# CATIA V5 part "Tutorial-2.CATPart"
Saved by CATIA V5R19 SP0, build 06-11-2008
Part number: c11tut2
Bounding box of the stored display mesh (mm): x -175 to 0, y -36.667 to 105, z 0 to 36.632
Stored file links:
  D:\Shriniwas\v5_r19\Part files\c11\c11tut2.CATPart
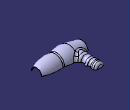
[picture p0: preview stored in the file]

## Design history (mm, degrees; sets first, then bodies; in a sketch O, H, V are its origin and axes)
Body1 (main body)
  Plane1: type Offset, Offset 75, RefPlane yz-plane, reversed
  Plane2: type Offset, Offset 125, RefPlane yz-plane, reversed
  Plane3: type Offset, Offset 175, RefPlane yz-plane, reversed
  Sketch1 on yz-plane, origin (0, 0, 0), H (0, 1, 0), V (0, 0, 1)
    arc A1 centre (0, 0) radius 20 from (20, 0) to (-20, 0) ccw
    point P1 (-20, 0)
    point P2 (20, 0)
    radius A1 = 20
    coincidence: P1 H, P2 H
  Sketch2 on Plane1, origin (-75, 0, 0), H (0, 1, 0), V (0, 0, 1)
    arc A1 centre (0, 0) radius 30 from (30, 0) to (-30, 0) ccw
    point P1 (-30, 0)
    point P2 (30, 0)
    radius A1 = 30
    coincidence: P1 H, P2 H
  Sketch3 on Plane2, origin (-125, 0, 0), H (0, 1, 0), V (0, 0, 1)
    arc A1 centre (0, 0) radius 35 from (35, 0) to (-35, 0) ccw
    point P1 (-35, 0)
    point P2 (35, 0)
    radius A1 = 35
    coincidence: P1 H, P2 H
  Sketch4 on Plane3, origin (-175, 0, 0), H (0, 1, 0), V (0, 0, 1)
    arc A1 centre (0, 0) radius 25 from (25, 0) to (-25, 0) ccw
    point P1 (-25, 0)
    point P2 (25, 0)
    radius A1 = 25
    coincidence: P1 H, P2 H
  Sketch5 on xy-plane, origin (0, 0, 0), H (1, 0, 0), V (0, 1, 0)
    arc A1 centre (-53.2457, -93.0924) radius 125 from (0, 20) to (-75, 30) ccw
    point P2 (0, 20)
    point P3 (-75, 30)
    reference projected point E1 (0, 20) from Sketch1.P2
    reference projected point E2 (-75, 30) from Sketch2.P2
    line L1 (-175, 25) -> (-125, 35)
    point P4 (-175, 25)
    point P5 (-125, 35)
    reference projected point E3 (-125, 35) from Sketch3.P2
    reference projected point E4 (-175, 25) from Sketch4.P2
    arc A2 centre (-108.1667, -49.1667) radius 85.8335 from (-75, 30) to (-125, 35) ccw
    radius A1 = 125
    coincidence: P2 V, P2 E1, P3 E2, P5 E3, E4 P4
    tangency: A2 L1
  Sketch6 on xy-plane, origin (0, 0, 0), H (1, 0, 0), V (0, 1, 0)
    reference projected line E1 (-125, 35) -> (-175, 25) from Sketch5.L1
    point P1 (-125, 35)
    point P2 (-175, 25)
    reference projected arc E2 centre (-108.1667, -49.1667) radius 85.8335 from (-75, 30) to (-125, 35) ccw from Sketch5.A2
    point P3 (-75, 30)
    point P4 (-125, 35)
    reference projected arc E3 centre (-53.2457, -93.0924) radius 125 from (0, 20) to (-75, 30) ccw from Sketch5.A1
    point P5 (0, 20)
    point P6 (-75, 30)
    point P7 (-75, -30)
    point P8 (0, -20)
    point P9 (-125, -35)
    point P10 (-75, -30)
    point P11 (-175, -25)
    point P12 (-125, -35)
    arc A1 centre (-53.2457, 93.0924) radius 125 from (0, -20) to (-75, -30) cw
    arc A2 centre (-108.1667, 49.1667) radius 85.8335 from (-75, -30) to (-125, -35) cw
    line L1 (-125, -35) -> (-175, -25)
    symmetry: P6 P7 H, P5 P8 H, E3 A1 H, P4 P9 H, P3 P10 H, E2 A2 H, P2 P11 H, P1 P12 H, E1 L1 H
  Loft1: Sections (Sketch1; Sketch2; Sketch3; Sketch4), Guides (Sketch5; Sketch6)
  Sketch7 on xy-plane, origin (0, 0, 0), H (1, 0, 0), V (0, 1, 0)
    line L1 (-160, 10) -> (-160, 105)
    point P1 (-160, 10)
    point P2 (-160, 105)
    reference projected line E1 (-175, -25) -> (-175, 25) from edge of Loft1
    reference projected point E2 (-175, 25) from vertex [face of Loft1]
    distance P1 E1 = 15
    distance E2 P1 V = 15
    distance H P2 = 105
    vertical: L1 V
  Sketch8 on xy-plane, origin (0, 0, 0), H (1, 0, 0), V (0, 1, 0)
    point P1 (-125, 105)
    construction line L1 (-125, 105) -> (-110.3491, 0.7536)
    line L2 (-125, 105) -> (-123.011, 90.8478)
    point P3 (-123.011, 90.8478)
    arc A1 centre (-129.9429, 89.8736) radius 7 from (-125.3895, 84.5571) to (-123.011, 90.8478) ccw
    point P5 (-123.011, 90.8478)
    arc A2 centre (-121.4865, 80) radius 6 from (-125.3895, 84.5571) to (-123.3627, 74.3009) ccw
    point P7 (-121.4865, 80)
    arc A3 centre (-124.8481, 69.7891) radius 4.75 from (-122.6028, 65.6033) to (-123.3627, 74.3009) ccw
    arc A4 centre (-118.3485, 57.6723) radius 9 from (-122.6028, 65.6033) to (-122.4134, 49.6426) ccw
    point P11 (-118.3485, 57.6723)
    arc A5 centre (-127.8333, 38.9362) radius 12 from (-115.9501, 40.6063) to (-122.4134, 49.6426) ccw
    construction line L3 (-160, 10) -> (-111.6486, 10)
    point P15 (-160, 10)
    line L4 (-111.6486, 10) -> (-115.9501, 40.6063)
    reference projected point E1 (-160, 10) from Sketch7.P1
    construction line L5 (-160, 105) -> (-125, 105)
    point P17 (-160, 105)
    point P18 (-125, 105)
    reference projected point E2 (-160, 105) from Sketch7.P2
    radius A1 = 7
    radius A2 = 6
    radius A3 = 4.75
    radius A4 = 9
    radius A5 = 12
    length L5 = 35
    distance P7 L5 = 25
    angle L5 L1 = 98
    parallelism: L2 L1
    tangency: A1 L1, A2 A1, A2 A3, A3 L1, A4 A3, A5 A4, L4 A5
    coincidence: P5 L1, P5 P3, P7 L1, P11 L1, P15 E1, P17 E2, P1 P18, L1 L4
    horizontal: L3 H, L5 H
  Plane4: type Offset, Offset 105, RefPlane zx-plane
  Sketch9 on Plane4, origin (0, 105, 0), H (-1, 0, 0), V (0, 0, 1)
    arc A1 centre (142.5, 0) radius 17.5 from (160, 0) to (125, 0) ccw
    point P2 (160, 0)
    point P3 (125, 0)
    reference projected point E1 (125, 0) from Sketch8.P1
    reference projected point E2 (160, 0) from Sketch7.P2
    radius A1 = 17.5
    coincidence: P3 E1, P2 E2
  Sweep1: type Unspec, Guide (Sketch7; Sketch8), Profile Sketch9, FittingPoints (Sketch7.P2; Sketch8.P1)
  Trim1: Trimmed (Sweep1; Loft1)
  Line1: type PtPt, SecondPoint vertex [face of Loft1], FirstPoint vertex [face of Loft1]
  Fill1: Boundary (edge of Loft1; Line1)
  Line2: type PtPt, SecondPoint vertex [face of Sweep1], FirstPoint vertex [face of Sweep1]
  Fill2: Boundary (edge of Sweep1; Line2)
  Line3: type PtPt, SecondPoint vertex [face of Loft1], FirstPoint vertex [face of Loft1]
  Fill3: Boundary (Line3; edge of Loft1)
  Fill4: Boundary (edge of Sweep1; edge of Sweep1; edge of Sweep1; edge of Sweep1; edge of Sweep1; edge of Sweep1; edge of Sweep1; Line2; edge of Sweep1; edge of Loft1; Line3; edge of Loft1; edge of Loft1; edge of Loft1; Line1; edge of Loft1; edge of Loft1)
  Join1: Elements (Fill4; Fill3; Trim1; Fill1; Fill2)
  CloseSurface1: CloseElement Join1
  Fillet1: radius 8, on edge [face of CloseSurface1 | face of CloseSurface1]
  Fillet2: radius 12, on edge [face of CloseSurface1 | face of CloseSurface1] (x2)
  Shell1: ExtOffset 0, IntOffset 1, Face (face of CloseSurface1; face of CloseSurface1; face of CloseSurface1)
